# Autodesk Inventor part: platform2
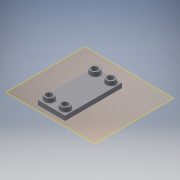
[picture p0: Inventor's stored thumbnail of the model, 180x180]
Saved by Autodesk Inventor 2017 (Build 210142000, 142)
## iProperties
Created: 2017-05
Part Number: platform2
Material: Generic
Document SubType Name: Modeling
Designer: 1717440
Density: 1 g/cm^3
Appearance: Default
Author: 1717440
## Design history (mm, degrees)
workplane "Work Plane2"
sketch "Sketch4"
  geometry: L1 (-19.592, 26.016)-(-19.592, -98.984) reference; L2 (-19.592, -98.984)-(40.408, -98.984) reference; L3 (40.408, -98.984)-(40.408, 26.016) reference; L4 (40.408, 26.016)-(-19.592, 26.016) reference; C1 r 10 at (-7.092, -86.484) reference; C2 r 10 at (27.908, -86.484) reference; C3 r 10 at (-7.092, 13.516) reference; C4 r 10 at (27.908, 13.516) reference; C5 r 6.425 at (-7.092, -86.484); C6 r 6.425 at (-7.092, 13.516); C7 r 6.425 at (27.908, 13.516); C8 r 6.425 at (27.908, -86.484); 1 further point
  constraints: 4 centre point, 3 coincident
  dimensions: "d19" = 12.85 diameter of C5; "d20" = 12.85 diameter of C6
extrude "Extrusion4" new body sketch "Sketch4" distance "d21" = 10; taper "d22" = 0 deg
sketch "Sketch5"
  geometry: C1 r 10 at (-27.908, 13.516) reference; C2 r 10 at (7.092, 13.516) reference; C3 r 10 at (-27.908, -86.484) reference; C4 r 10 at (7.092, -86.484) reference; C5 r 10 at (7.092, 13.516) reference; C6 r 6.425 at (7.092, 13.516); C7 r 6.425 at (-27.908, 13.516); C8 r 6.425 at (-27.908, -86.484); C9 r 6.425 at (7.092, -86.484); 1 further point
  constraints: 4 centre point, 4 coincident
  dimensions: "d23" = 12.85 diameter of C6; "d24" = 12.85 diameter of C8
extrude "Extrusion5" join sketch "Sketch5" distance "d25" = 20; taper "d26" = 0 deg
fillet "Fillet1" dims "d27" = 2
fillet "Fillet2" dims "d28" = 1
body "Solid2"
node "Reference1"
node "Reference2"
node "Reference3"
node "Reference4"
node "Reference5"
